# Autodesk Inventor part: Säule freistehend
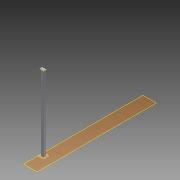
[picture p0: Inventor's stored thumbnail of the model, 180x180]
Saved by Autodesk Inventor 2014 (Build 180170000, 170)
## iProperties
Created: 2013-09
Part Number: Säule freistehend
Material: Stahl
Document SubType Name: Modeling
Designer: Stefan Tammegger
Mass: 16543.3 g
Surface Area: 14067.9 cm^2
Volume: 2107.43 cm^3
Density: 7.85 g/cm^3
Appearance: Stahl
Author: Stefan Tammegger
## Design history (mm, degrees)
node "Blöcke"
  sketch "FR 80_80_3"
    geometry: L1 (-331.019, -2889.589)-(-257.019, -2889.589); L2 (-254.019, -2892.589)-(-254.019, -2966.589); L3 (-257.019, -2969.589)-(-331.019, -2969.589); L4 (-334.019, -2966.589)-(-334.019, -2892.589); L5 (-257.019, -2892.589)-(-331.019, -2892.589); L6 (-331.019, -2892.589)-(-331.019, -2966.589); L7 (-331.019, -2966.589)-(-257.019, -2966.589); L8 (-257.019, -2966.589)-(-257.019, -2892.589); A1 r 3 centre (-331.019, -2892.589) between (-331.019, -2889.589) and (-334.019, -2892.589); A2 r 3 centre (-257.019, -2892.589) between (-254.019, -2892.589) and (-257.019, -2889.589); A3 r 3 centre (-257.019, -2966.589) between (-257.019, -2969.589) and (-254.019, -2966.589); A4 r 3 centre (-331.019, -2966.589) between (-334.019, -2966.589) and (-331.019, -2969.589); 4 further points
    constraints: 16 end point, 8 point on circle, 8 tangent, 6 point on line, 4 centre point, 4 parallel, 3 equal radius, 2 perpendicular, 1 horizontal, 1 midpoint, 3 other
    dimensions: "d0" = 80 distance of point (-254.019, -2969.589) point (-334.019, -2969.589); "d1" = 80 distance of point (-254.019, -2889.589) point (-254.019, -2969.589); "d2" = 3 distance between parallel lines of L1 L5; "d3" = 3 radius of A1
workplane "Arbeitsebene1"
sketch "Skizze1"
  geometry: L1 (-370, 0)-(-370, -3300) reference; L2 (0, -3300)-(-370, -3300) reference; L3 (0, 0)-(0, -3300) reference; L4 (-258, -2924)-(-4085.659, -2924) reference; L5 (-258, -2996)-(-4067.707, -2996) reference; L6 (-258, -3000)-(-4066.71, -3000) reference; L7 (-258, -2920)-(-4086.656, -2920) reference; L8 (-210, -1280)-(-210, -3780) reference; L9 (-170, -3780)-(-170, -1280) reference; L10 (-290, -2920)-(-290, -3000)
  constraints: 2 end point, 1 horizontal, 2 other
  dimensions: "d4" = 80 distance between parallel lines of L8 L10
  node "Referenz1"
  node "Referenz2"
  node "Referenz3"
  node "Referenz4"
  node "Referenz5"
  node "Referenz6"
  node "Referenz7"
  node "Referenz8"
  node "Referenz9"
  node "FR 80_80_3:1" dims "d4" = 80
workplane "Arbeitsebene2"
extrude "Extrusion1" new body sketch "Skizze1" stored distance "d5" = 10; taper "d6" = 0 deg
workplane "Arbeitsebene3"
sketch "Skizze2"
  geometry: L1 (-330, -2923)-(-330, -2997) reference; L2 (-250, -2997)-(-250, -2923) reference; L3 (-258, -2920)-(-4086.656, -2920) reference; L4 (-258, -3000)-(-4066.71, -3000) reference; L5 (-360, -2880)-(-220, -2880); L6 (-220, -2880)-(-220, -3040); L7 (-220, -3040)-(-360, -3040); L8 (-360, -3040)-(-360, -2880); L9 (-327, -2923)-(-253, -2923) reference; L10 (-253, -2997)-(-327, -2997) reference; L11 (-290, -2923)-(-290, -2997); L12 (-330, -2960)-(-250, -2960); 1 further point
  constraints: 12 end point, 4 midpoint, 2 parallel, 1 horizontal, 1 perpendicular, 2 other
  dimensions: "d7" = 140 distance of L5.start L5.end; "d8" = 160 distance of L5.end L6.end
extrude "Extrusion2" new body sketch "Skizze2" distance "d9" = 10; taper "d10" = 0 deg
sketch "Skizze3"
  geometry: L1 (-220, -2880)-(-360, -2880) reference; L2 (-360, -2880)-(-360, -3040) reference; L3 (-360, -3040)-(-220, -3040) reference; L4 (-220, -3040)-(-220, -2880) reference; L5 (-240, -3020)-(-340, -3020); L6 (-340, -3020)-(-340, -2900); L7 (-340, -2900)-(-240, -2900); L8 (-240, -2900)-(-240, -3020); 1 further point
  constraints: 8 end point, 3 other
  dimensions: "d11" = 20 distance between parallel lines of L3 L5
hole "Bohrung1" sketch "Skizze3" at (-340, -2900), (-340, -3020), (-240, -3020), (-240, -2900) diameter "d12" = 14; stored, may be unused: countersink angle "d16" = 90 deg, drill point angle "d18" = 118 deg; dims "d13" = 6, "d14" = 4, "d15" = 2, "d17" = 8
workplane "Arbeitsebene4"
feature "Trennen1"
workplane "Arbeitsebene5"
feature "Trennen2"
sketch "Skizze4"
  geometry: L1 (74, -3)-(0, -3) reference; L2 (0, -77)-(74, -77) reference; L3 (77, -3)-(77, -77) reference; L4 (-3, -77)-(-3, -3) reference; L5 (37, -3)-(37, -77); L6 (-3, -40)-(77, -40); L7 (-43, 0)-(77, 0); L8 (77, -80)-(-43, -80); L9 (-43, -80)-(-43, 0); L10 (77, -80)-(77, 0); 1 further point
  constraints: 12 end point, 4 midpoint, 1 horizontal, 1 parallel, 1 point on line, 1 other
  dimensions: "d21" = 120 distance of L8.end L8.start; "d22" = 80 distance of L8.start L7.end
extrude "Extrusion3" new body sketch "Skizze4" distance "d23" = 10; taper "d24" = 0 deg
sketch "Skizze6"
  geometry: L1 (43, 0)-(-77, 0) reference; L2 (-77, 0)-(-77, -80) reference; L3 (-77, -80)-(43, -80) reference; L4 (43, -80)-(43, 0) reference; L5 (23, -60)-(-57, -60); L6 (-57, -60)-(-57, -20); L7 (-57, -20)-(23, -20); L8 (23, -20)-(23, -60); 1 further point
  constraints: 8 end point, 3 other
  dimensions: "d33" = 20 distance between parallel lines of L4 L8
hole "Bohrung3" sketch "Skizze6" at (23, -60), (23, -20) diameter "d34" = 14; stored, may be unused: countersink angle "d38" = 90 deg, drill point angle "d40" = 118 deg; dims "d35" = 6, "d36" = 4, "d37" = 2, "d39" = 8
node "Volumenkörper1"
node "Referenz10"
node "Referenz11"
node "Volumenkörper2"
node "Volumenkörper3"
other parameters: "d19" = 0
